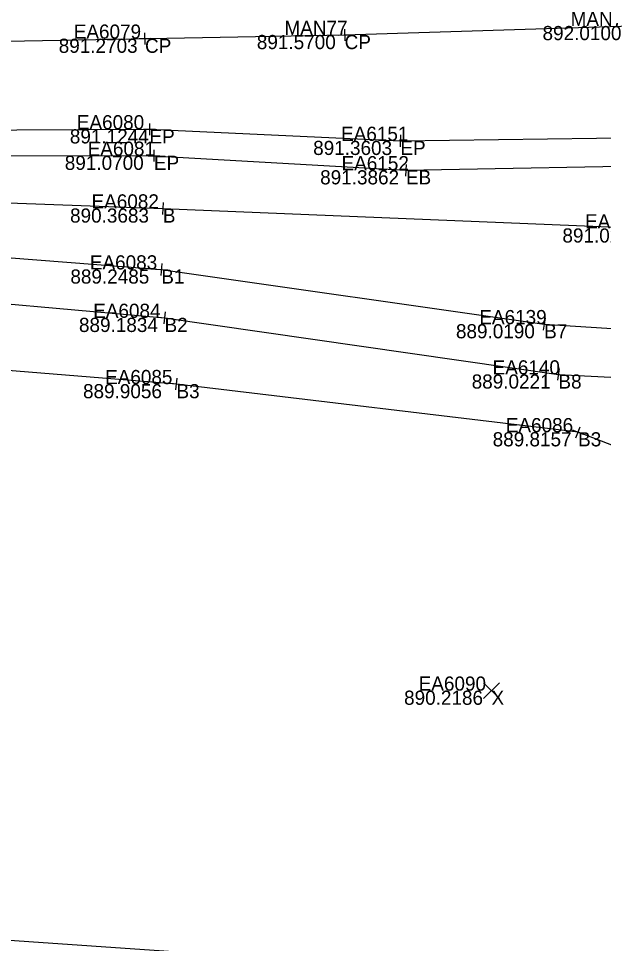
# Model space of a CAD drawing. Extents: x 179044 to 189691, y 286531 to 301257.
# Drawn here: x 180120 to 180169.6, y 300512.8 to 300591.3 of the extents above; entities that cross this region are included whole.
import ezdxf

# ---------------------------------------------------------------- set-up
doc = ezdxf.new("R2010")
doc.units = 0
for name, color, linetype in [('PV_X_COP', 7, 'Continuous'), ('PV_X_EOP', 7, 'Continuous'), ('PV_X_Shoulder_Aggregate', 7, 'Continuous'), ('RD_X_Fence', 7, 'Continuous'), ('SV_X_Break_Lines', 7, 'Continuous'), ('SV_X_Random_Point', 7, 'Continuous'), ('SV_X_Shot_Marker', 7, 'Continuous'), ('SV_X_Text_Comment', 7, 'Continuous'), ('SV_X_Text_Elevation', 7, 'Continuous'), ('SV_X_Text_Name', 7, 'Continuous')]:
    doc.layers.add(name, color=color, linetype=linetype)

msp = doc.modelspace()

# ---------------------------------------------------------------- linework, layer by layer
at = {"layer": 'PV_X_COP'}
msp.add_lwpolyline([(179370.611, 300584.893), (179476.831, 300585.936), (179562.951, 300586.92), (179659.852, 300587.603), (179771.173, 300587.773), (179881.154, 300588.595), (179985.728, 300588.166), (180079.826, 300588.612), (180147.691, 300589.874), (180172.034, 300590.636), (180187.456, 300591.905), (180203.618, 300593.325)], dxfattribs=at)
at = {"layer": 'PV_X_EOP'}
msp.add_lwpolyline([(179371.146, 300578.051), (179477.168, 300579.528), (179563.012, 300579.455), (179660.626, 300579.907), (179772.349, 300580.843), (179883.302, 300581.216), (179986.953, 300581.659), (180080.461, 300581.624), (180131.142, 300581.875), (180152.421, 300580.897), (180177.372, 300581.245), (180192.481, 300580.813), (180205.116, 300578.916), (180211.895, 300576.366), (180217.061, 300570.924), (180226.256, 300546.032), (180252.64, 300475.662), (180284.891, 300388.784), (180312.046, 300315.753), (180341.998, 300235.308)], dxfattribs=at)
at = {"layer": 'PV_X_Shoulder_Aggregate'}
msp.add_lwpolyline([(179563.451, 300578.229), (179660.977, 300578.016), (179772.748, 300578.901), (179883.7, 300579.446), (179986.895, 300579.719), (180080.262, 300579.655), (180131.517, 300579.632), (180152.892, 300578.404), (180177.169, 300578.87), (180192.854, 300577.824), (180203.732, 300575.396), (180212.869, 300569.272), (180224.05, 300544.426), (180250.422, 300474.503), (180282.665, 300386.992), (180309.922, 300313.986), (180339.844, 300234.334)], dxfattribs=at)
at = {"layer": 'RD_X_Fence'}
msp.add_lwpolyline([(179565.425, 300550.823), (179667.832, 300544.252), (179812.225, 300533.926), (179896.206, 300528.356), (179941.193, 300525.399), (180078.773, 300515.902), (180168.337, 300509.719), (180196.88, 300447.723), (180266.667, 300296.146), (180285.875, 300252.935)], dxfattribs=at)
at = {"layer": 'SV_X_Break_Lines'}
for points in [[(179565.115, 300573.15), (179662.025, 300574.398), (179773.068, 300575.457), (179882.867, 300576.482), (179986.954, 300576.827), (180079.906, 300577.073), (180132.276, 300575.162), (180173.558, 300573.472), (180187.352, 300573.774), (180198.853, 300570.766)], [(179565.766, 300571.109), (179663.199, 300570.888), (179773.087, 300572.831), (179882.326, 300573.106), (179987.447, 300574.391), (180079.006, 300574.101), (180132.144, 300569.99), (180164.614, 300565.351), (180185.409, 300564.026)], [(179565.763, 300567.872), (179663.335, 300568.017), (179772.883, 300569.466), (179881.609, 300569.697), (179987.857, 300571.139), (180079.155, 300570.638), (180132.418, 300565.887), (180165.824, 300561.088), (180185.221, 300560.101)], [(180320.902, 300212.184), (180282.069, 300307.438), (180254.033, 300376.286), (180214.216, 300457.225), (180192.833, 300518.475), (180187.002, 300524.649), (180178.544, 300551.918), (180167.492, 300556.189), (180133.433, 300560.27), (180078.668, 300564.705), (179988.563, 300564.714), (179881.16, 300565.14), (179774.574, 300564.41), (179665.201, 300563.792), (179565.532, 300563.693)]]:
    msp.add_lwpolyline(points, dxfattribs=at)
at = {"layer": 'SV_X_Random_Point'}
for p, q in [((180159.483, 300533.606), (180160.817, 300534.941)), ((180159.483, 300534.941), (180160.817, 300533.606))]:
    msp.add_line(p, q, dxfattribs=at)
at = {"layer": 'SV_X_Shot_Marker'}
for p, q in [((180130.775, 300589.06), (180130.756, 300590.059)), ((180147.682, 300590.374), (180147.7, 300589.374)), ((180131.265, 300589.569), (180130.266, 300589.55)), ((180130.765, 300589.559), (180130.765, 300589.559)), ((180147.191, 300589.865), (180148.191, 300589.884)), ((180147.691, 300589.874), (180147.691, 300589.874)), ((180131.14, 300582.375), (180131.145, 300581.375)), ((180130.643, 300581.873), (180131.642, 300581.878)), ((180131.142, 300581.875), (180131.142, 300581.875)), ((180152.444, 300581.397), (180152.398, 300580.398)), ((180151.922, 300580.92), (180152.921, 300580.874)), ((180152.421, 300580.897), (180152.421, 300580.897)), ((180131.518, 300580.132), (180131.517, 300579.132)), ((180131.017, 300579.632), (180132.017, 300579.632)), ((180131.517, 300579.632), (180131.517, 300579.632)), ((180152.393, 300578.433), (180153.391, 300578.375)), ((180152.921, 300578.903), (180152.863, 300577.905)), ((180152.892, 300578.404), (180152.892, 300578.404)), ((180131.776, 300575.18), (180132.776, 300575.144)), ((180132.294, 300575.662), (180132.258, 300574.662)), ((180132.276, 300575.162), (180132.276, 300575.162)), ((180132.182, 300570.489), (180132.105, 300569.491)), ((180131.645, 300570.029), (180132.642, 300569.951)), ((180132.144, 300569.99), (180132.144, 300569.99)), ((180131.92, 300565.932), (180132.916, 300565.843)), ((180132.462, 300566.385), (180132.373, 300565.389)), ((180132.418, 300565.887), (180132.418, 300565.887)), ((180164.685, 300565.846), (180164.543, 300564.856)), ((180164.119, 300565.422), (180165.109, 300565.281)), ((180164.614, 300565.351), (180164.614, 300565.351)), ((180165.329, 300561.159), (180166.319, 300561.017)), ((180165.895, 300561.583), (180165.753, 300560.593)), ((180165.824, 300561.088), (180165.824, 300561.088)), ((180133.93, 300560.21), (180132.937, 300560.329)), ((180133.374, 300559.773), (180133.493, 300560.766)), ((180133.433, 300560.27), (180133.433, 300560.27)), ((180167.958, 300556.008), (180167.026, 300556.369)), ((180167.312, 300555.722), (180167.672, 300556.655)), ((180167.492, 300556.189), (180167.492, 300556.189))]:
    msp.add_line(p, q, dxfattribs=at)

# ---------------------------------------------------------------- texts
at = {"layer": 'SV_X_Text_Comment'}
for s, p in [('CP', (180130.765, 300588.359)), ('CP', (180147.691, 300588.674)), ('EP', (180131.142, 300580.675)), ('EP', (180152.421, 300579.697)), ('EP', (180131.517, 300578.432)), ('EB', (180152.892, 300577.204)), ('B', (180132.276, 300573.962)), ('B1', (180132.144, 300568.79)), ('B2', (180132.418, 300564.687)), ('B7', (180164.614, 300564.151)), ('B8', (180165.824, 300559.888)), ('B3', (180133.433, 300559.07)), ('B3', (180167.492, 300554.989)), ('X', (180160.15, 300533.074))]:
    msp.add_text(s, height=1.2, dxfattribs=at).set_placement(p)
at = {"layer": 'SV_X_Text_Elevation'}
for s, p in [('892.0100', (180164.476, 300589.436)), ('891.2703', (180123.444, 300588.359)), ('891.5700', (180140.247, 300588.674)), ('891.1244', (180124.388, 300580.675)), ('891.3603', (180145.024, 300579.697)), ('891.0700', (180123.959, 300578.432)), ('891.3862', (180145.617, 300577.204)), ('890.3683', (180124.406, 300573.962)), ('891.0226', (180166.161, 300572.272)), ('889.2485', (180124.434, 300568.79)), ('889.1834', (180125.162, 300564.687)), ('889.0190', (180157.132, 300564.151)), ('889.0221', (180158.466, 300559.888)), ('889.9056', (180125.506, 300559.07)), ('889.8157', (180160.246, 300554.989)), ('890.2186', (180152.734, 300533.074))]:
    msp.add_text(s, height=1.2, dxfattribs=at).set_placement(p)
at = {"layer": 'SV_X_Text_Name'}
for s, p in [('MAN76', (180166.857, 300590.636)), ('EA6079', (180124.719, 300589.559)), ('MAN77', (180142.589, 300589.874)), ('EA6080', (180124.982, 300581.875)), ('EA6151', (180147.389, 300580.897)), ('EA6081', (180125.899, 300579.632)), ('EA6152', (180147.432, 300578.404)), ('EA6082', (180126.229, 300575.162)), ('EA6145', (180168.079, 300573.472)), ('EA6083', (180126.088, 300569.99)), ('EA6084', (180126.371, 300565.887)), ('EA6139', (180159.116, 300565.351)), ('EA6140', (180160.24, 300561.088)), ('EA6085', (180127.377, 300560.27)), ('EA6086', (180161.36, 300556.189)), ('EA6090', (180153.971, 300534.274))]:
    msp.add_text(s, height=1.2, dxfattribs=at).set_placement(p)

doc.saveas('drawing.dxf')
